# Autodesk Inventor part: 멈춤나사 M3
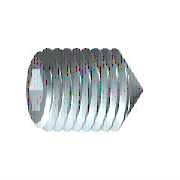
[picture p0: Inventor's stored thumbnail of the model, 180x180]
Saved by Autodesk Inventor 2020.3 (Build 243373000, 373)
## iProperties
Created: 2012-02
Part Number: 멈춤나사 M3
Material: 강철, 연강
Description: 6각 소켓 머리 없는 멈춤 나사
Document SubType Name: Modeling
Standard: KS B 1028
Designer: test
Standards Organization: KS
Language: ko-KR
Size Designation: 원추점 M3x8
Categories: <MemberInstance><Categories><Category DisplayName="조임쇠" InternalName="e4da775c-781d-43d5-af7c-5136215cf5a6" Mnemonic="FSTN"><Category DisplayName="볼트" InternalN
Density: 1 g/cm^3
Appearance: 강철
IsCustomPart: 1
Author: test
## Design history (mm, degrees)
sketch "스케치1"
  geometry: L1 (0, 0)-(5.5, 0); L2 (8, 0.866)-(8, 1.5); L3 (8, 1.5)-(0, 1.5); L4 (8, 0.866)-(6, 0.866); L5 (6, 0.866)-(5.5, 0); L6 (0, -0.3)-(0, 1.8) reference; L7 (0, 1.5)-(0, 0)
  constraints: 13 end point, 3 parallel, 1 collinear, 1 perpendicular, 1 point on line
  dimensions: "d0" = 2 distance of L2.start L4.end (= INTI); "d1" = 60 deg angle of L5 L1; "d2" = 3 diameter of L3 L1 (= NND); "d3" = 1.73205 diameter of L4 L1 (= 1.1547 x SW); "d5" = 8 distance from line of L2 L3.end (= NLG)
revolve "본체" sketch "스케치1" stored, may be unused: angle "d6" = 90 deg
sketch "스케치2"
  geometry: L1 (-0.433, 0.75)-(0.433, 0.75); L2 (0.433, 0.75)-(0.866, 0); L3 (0.866, 0)-(0.433, -0.75); L4 (0.433, -0.75)-(-0.433, -0.75); L5 (-0.433, -0.75)-(-0.866, 0); L6 (-0.866, 0)-(-0.433, 0.75); 3 further points
  constraints: 12 end point, 1 coincident, 1 horizontal, 13 other
extrude "슬롯" join sketch "스케치2" taper "d7" = 0 deg; stored distance "d21" = 10
workaxis "Work Axis1"
workplane "Work Plane1"
sketch "스케치4"
  geometry: L1 (0, 0.15)-(-1.35, 1.5) reference; L2 (0, -0.15)-(-1.35, -1.5) reference; L3 (-1.35, -1.5)-(0.15, 0); L4 (-1.35, 1.5)-(0.15, 0); 2 further points
  constraints: 4 end point, 1 coincident, 1 collinear, 1 horizontal alignment
body "Solid1"
feature "스레드" dims "d12" = 8 (= NLG), "d13" = 0
chamfer "모따기1" distance "d8" = 1.35 (computed from NND, SPD, FAWI); stored, may be unused: angle "d9" = 45 deg (= FAWI), second distance "d34" = 1.35 (computed from NND, SPD, FAWI)
chamfer "모따기2" distance "d10" = 0.30673 (= -0.5 x GD1 + 0.5 x NND); stored, may be unused: angle "d11" = 45 deg (= FAWI), second distance "d35" = 0.30673 (= -0.5 x GD1 + 0.5 x NND)
other parameters: "NND" = 3 [user parameter; used in 5 equation terms], "NLG" = 8 [user parameter; used in 2 equation terms], "INTI" = 2 [user parameter; used in 1 equation term], "FAWI" = 45 deg [user parameter; used in 4 equation terms], "SW" = 1.5 [user parameter; used in 2 equation terms], "GD1" = 2.38655 (= THREADDIA - 1.2269 x PTC) [user parameter; used in 2 equation terms], "d4" = 0, "FAWI1" = 45 deg [user parameter], "SPD" = 0.3 [user parameter; used in 2 equation terms], "d36" = 0, "d37" = 0, "GUL" = 0.30673 (= 0.61345 x PTC) [user parameter], "TOA" = 30 deg [user parameter], "THREADDIA" = 3 [user parameter; used in 1 equation term], "PTC" = 0.5 [user parameter; used in 4 equation terms], "GAL" = 0.30673 (= 0.61345 x PTC) [user parameter], "E0" = 1.7325 (= 1.155 x SW) [user parameter]
